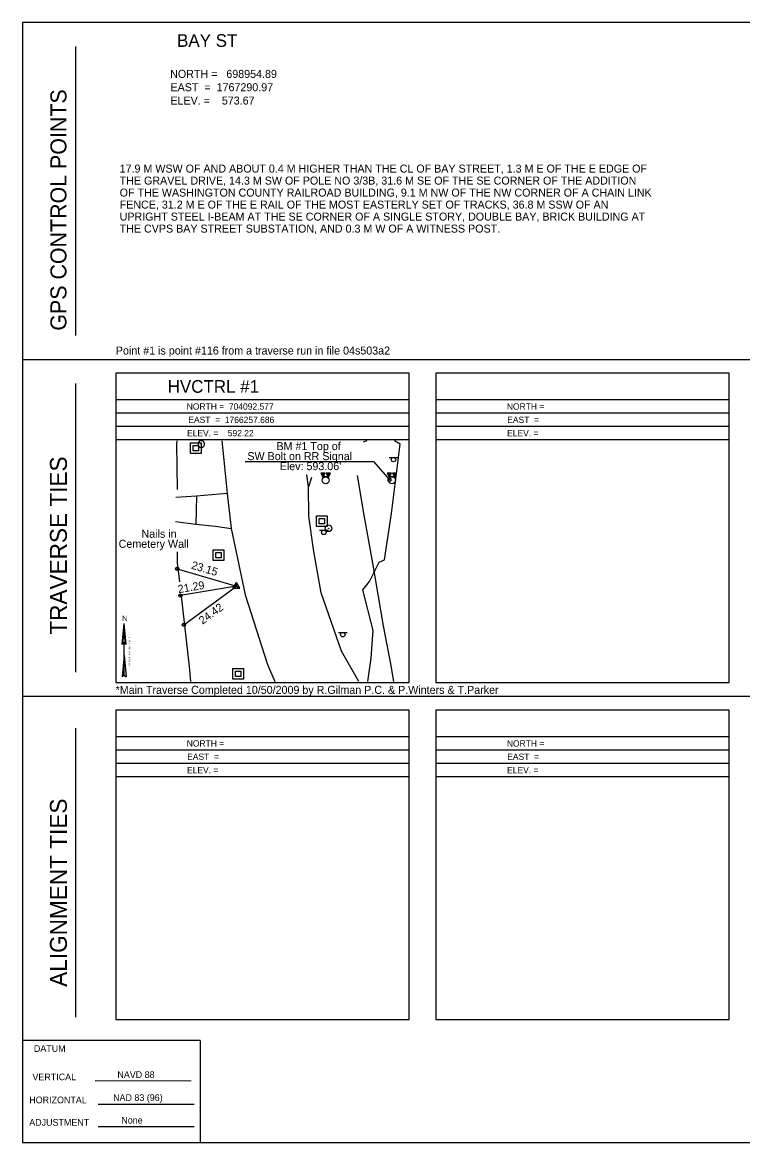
# Model space of a CAD drawing. Extents: x 1765437 to 1766077, y 703827 to 704247.
# Drawn here: x 1765437.5 to 1765707.5, y 703827.4 to 704247.4 of the extents above; entities that cross this region are included whole.
import ezdxf

# ---------------------------------------------------------------- set-up
doc = ezdxf.new("R2010")
doc.units = 0
for name, color, linetype in [('C_C', 7, 'Continuous'), ('CBP', 7, 'Continuous'), ('CPBM', 7, 'Continuous'), ('CPSM', 7, 'Continuous'), ('Default', 7, 'Continuous'), ('DS', 7, 'Continuous'), ('LW', 7, 'Continuous'), ('NBL1', 7, 'Continuous'), ('NBL2', 7, 'Continuous'), ('NNA_P', 7, 'Continuous'), ('PET', 7, 'Continuous'), ('RDG', 7, 'Continuous'), ('RDP', 7, 'Continuous'), ('RGP', 7, 'Continuous'), ('RRC', 7, 'Continuous'), ('SSGN', 7, 'Continuous'), ('TCSH', 7, 'Continuous')]:
    doc.layers.add(name, color=color, linetype=linetype)

msp = doc.modelspace()

# ---------------------------------------------------------------- linework, layer by layer
at = {"layer": 'C_C'}
for p, q in [((1765520.93, 704082.77), (1765569.04, 704082.77)), ((1765569.04, 704082.77), (1765575.07, 704075.83))]:
    msp.add_line(p, q, dxfattribs=at)
at = {"layer": 'CBP'}
for centre, radius in [((1765495.52, 704042.53), 0.625), ((1765495.52, 704042.53), 0.0833), ((1765496.71, 704032.44), 0.625), ((1765496.71, 704032.44), 0.0833), ((1765498.01, 704021.53), 0.625), ((1765498.01, 704021.53), 0.0833)]:
    msp.add_circle(centre, radius, dxfattribs=at)
at = {"layer": 'CPBM'}
for p, q in [((1765574.57, 704075.33), (1765574.57, 704076.33)), ((1765574.57, 704076.33), (1765575.57, 704076.33)), ((1765575.07, 704075.83), (1765575.07, 704075.83)), ((1765575.07, 704075.83), (1765575.07, 704075.83)), ((1765575.57, 704076.33), (1765575.57, 704075.33)), ((1765575.57, 704075.33), (1765574.57, 704075.33))]:
    msp.add_line(p, q, dxfattribs=at)
at = {"layer": 'CPSM'}
for p, q in [((1765516.47, 704035.22), (1765517.72, 704037.39)), ((1765516.47, 704035.22), (1765517.72, 704035.95)), ((1765516.47, 704035.22), (1765518.97, 704035.22)), ((1765518.97, 704035.22), (1765517.72, 704037.39)), ((1765517.72, 704035.95), (1765517.72, 704037.39)), ((1765517.72, 704035.95), (1765517.72, 704035.95)), ((1765517.72, 704035.95), (1765518.97, 704035.22))]:
    msp.add_line(p, q, dxfattribs=at)
at = {"layer": 'Default'}
for p, q in [((1765495.52, 704042.53), (1765517.72, 704035.95)), ((1765517.72, 704035.95), (1765496.71, 704032.44)), ((1765498.01, 704021.53), (1765517.72, 704035.95))]:
    msp.add_line(p, q, dxfattribs=at)
at = {"layer": 'DS'}
for p, q in [((1765500.51, 704089.75), (1765504.51, 704089.75)), ((1765500.51, 704085.75), (1765500.51, 704089.75)), ((1765501.51, 704086.75), (1765501.51, 704088.75)), ((1765501.51, 704088.75), (1765503.51, 704088.75)), ((1765503.51, 704088.75), (1765503.51, 704086.75)), ((1765504.51, 704089.75), (1765504.51, 704085.75)), ((1765504.51, 704085.75), (1765500.51, 704085.75)), ((1765503.51, 704086.75), (1765501.51, 704086.75)), ((1765502.51, 704087.75), (1765502.51, 704087.75)), ((1765502.51, 704087.75), (1765502.51, 704087.75)), ((1765547.67, 704062.35), (1765551.67, 704062.35)), ((1765547.67, 704058.35), (1765547.67, 704062.35)), ((1765548.67, 704059.35), (1765548.67, 704061.35)), ((1765548.67, 704061.35), (1765550.67, 704061.35)), ((1765550.67, 704059.35), (1765548.67, 704059.35)), ((1765549.67, 704060.35), (1765549.67, 704060.35)), ((1765549.67, 704060.35), (1765549.67, 704060.35)), ((1765550.67, 704061.35), (1765550.67, 704059.35)), ((1765551.67, 704062.35), (1765551.67, 704058.35)), ((1765551.67, 704058.35), (1765547.67, 704058.35)), ((1765508.97, 704049.66), (1765512.97, 704049.66)), ((1765508.97, 704045.66), (1765508.97, 704049.66)), ((1765509.97, 704046.66), (1765509.97, 704048.66)), ((1765509.97, 704048.66), (1765511.97, 704048.66)), ((1765511.97, 704046.66), (1765509.97, 704046.66)), ((1765510.98, 704047.67), (1765510.98, 704047.67)), ((1765510.98, 704047.67), (1765510.98, 704047.67)), ((1765511.97, 704048.66), (1765511.97, 704046.66)), ((1765512.97, 704049.66), (1765512.97, 704045.66)), ((1765512.97, 704045.66), (1765508.97, 704045.66)), ((1765516.4, 704005.15), (1765520.4, 704005.15)), ((1765516.4, 704001.15), (1765516.4, 704005.15)), ((1765517.4, 704002.15), (1765517.4, 704004.15)), ((1765517.4, 704004.15), (1765519.4, 704004.15)), ((1765519.4, 704004.15), (1765519.4, 704002.15)), ((1765520.4, 704005.15), (1765520.4, 704001.15)), ((1765520.4, 704001.15), (1765516.4, 704001.15)), ((1765519.4, 704002.15), (1765517.4, 704002.15)), ((1765518.4, 704003.15), (1765518.4, 704003.15)), ((1765518.4, 704003.15), (1765518.4, 704003.15))]:
    msp.add_line(p, q, dxfattribs=at)
at = {"layer": 'LW'}
for points in [[(1765495.34, 704090.48), (1765495.22, 704089.28), (1765495.48, 704072.19)], [(1765496.43, 704037.63), (1765495.6, 704044.8), (1765495.67, 704048.86)], [(1765500.62, 704000.23), (1765500.12, 704005.87), (1765497.06, 704032.21), (1765497.02, 704032.52)]]:
    msp.add_lwpolyline(points, dxfattribs=at)
at = {"layer": 'NBL1'}
msp.add_lwpolyline([(1765437.47, 703827.37), (1766077.47, 703827.37), (1766077.47, 704247.37), (1765437.47, 704247.37)], close=True, dxfattribs=at)
at = {"layer": 'NBL2'}
for p, q in [((1765457.47, 704130.04), (1765457.47, 704238.37)), ((1765437.47, 704121.04), (1766077.47, 704121.04)), ((1765457.47, 704003.7), (1765457.47, 704112.04)), ((1765582.47, 704105.87), (1765472.47, 704105.87)), ((1765702.47, 704105.87), (1765592.47, 704105.87)), ((1765582.47, 704100.87), (1765472.47, 704100.87)), ((1765702.47, 704100.87), (1765592.47, 704100.87)), ((1765582.47, 704095.87), (1765472.47, 704095.87)), ((1765702.47, 704095.87), (1765592.47, 704095.87)), ((1765582.47, 704090.87), (1765472.47, 704090.87)), ((1765702.47, 704090.87), (1765592.47, 704090.87)), ((1765437.47, 703994.7), (1766077.47, 703994.7)), ((1765457.47, 703874.37), (1765457.47, 703982.7)), ((1765582.47, 703979.54), (1765472.47, 703979.54)), ((1765702.47, 703979.54), (1765592.47, 703979.54)), ((1765582.47, 703974.54), (1765472.47, 703974.54)), ((1765702.47, 703974.54), (1765592.47, 703974.54)), ((1765582.47, 703969.54), (1765472.47, 703969.54)), ((1765702.47, 703969.54), (1765592.47, 703969.54)), ((1765582.47, 703964.54), (1765472.47, 703964.54)), ((1765702.47, 703964.54), (1765592.47, 703964.54)), ((1765504.13, 703865.62), (1765437.47, 703865.62)), ((1765504.13, 703865.62), (1765504.13, 703827.37)), ((1765504.13, 703865.62), (1765504.13, 703827.37)), ((1765464.71, 703850.6), (1765500.71, 703850.57)), ((1765465.82, 703841.83), (1765501.82, 703841.83)), ((1765465.82, 703833.39), (1765501.82, 703833.36))]:
    msp.add_line(p, q, dxfattribs=at)
for points in [[(1765472.47, 703999.87), (1765582.47, 703999.87), (1765582.47, 704115.87), (1765472.47, 704115.87)], [(1765592.47, 703999.87), (1765702.47, 703999.87), (1765702.47, 704115.87), (1765592.47, 704115.87)], [(1765472.47, 703873.54), (1765582.47, 703873.54), (1765582.47, 703989.54), (1765472.47, 703989.54)], [(1765592.47, 703873.54), (1765702.47, 703873.54), (1765702.47, 703989.54), (1765592.47, 703989.54)]]:
    msp.add_lwpolyline(points, close=True, dxfattribs=at)
at = {"layer": 'NNA_P'}
for p, q in [((1765474.92, 704014.17), (1765475.62, 704021.96)), ((1765475.62, 704002.59), (1765475.62, 704021.96)), ((1765476.31, 704014.17), (1765475.62, 704021.96)), ((1765474.92, 704014.17), (1765475.62, 704014.94)), ((1765476.31, 704014.17), (1765475.62, 704014.94)), ((1765475.62, 704010.11), (1765474.9, 704001.95)), ((1765475.62, 704010.11), (1765476.34, 704001.95)), ((1765475.62, 704002.59), (1765474.9, 704001.95)), ((1765475.62, 704002.59), (1765476.34, 704001.95))]:
    msp.add_line(p, q, dxfattribs=at)
at = {"layer": 'PET'}
for points in [[(1765512.23, 704090.48), (1765513.03, 704083.29), (1765514.25, 704070.75), (1765515.71, 704057.63), (1765520.98, 704032.77), (1765529.29, 704006.59), (1765532.11, 704000.23)], [(1765567, 704000.23), (1765568.17, 704009.02), (1765568.93, 704019.33), (1765565.04, 704034.6), (1765567.58, 704037.74), (1765571.24, 704044.99), (1765573.24, 704045.81), (1765575.83, 704063.3), (1765579.14, 704089.21), (1765576.93, 704090.48)], [(1765566.62, 704090.48), (1765565.24, 704089.99)], [(1765545.88, 704076.8), (1765544.71, 704073.22), (1765544.08, 704077.7)], [(1765563.59, 704000.23), (1765557.14, 704011.59), (1765549.5, 704033.49), (1765546.73, 704048.99), (1765544.83, 704062.24), (1765544.71, 704073.22)]]:
    msp.add_lwpolyline(points, dxfattribs=at)
at = {"layer": 'RDG'}
for points in [[(1765502.77, 704069.8), (1765494.94, 704069.3)], [(1765494.81, 704060.21), (1765502.43, 704059.19)]]:
    msp.add_lwpolyline(points, dxfattribs=at)
at = {"layer": 'RDP'}
msp.add_lwpolyline([(1765514.25, 704070.75), (1765502.77, 704069.8), (1765502.43, 704059.19), (1765509.81, 704058.46), (1765515.71, 704057.63)], dxfattribs=at)
at = {"layer": 'RGP'}
for p, q in [((1765504.99, 704090.48), (1765504.13, 704090.48)), ((1765504.56, 704089.3), (1765504.56, 704089.3)), ((1765552.25, 704057.69), (1765552.25, 704057.69))]:
    msp.add_line(p, q, dxfattribs=at)
for centre, radius in [((1765504.56, 704089.3), 0.0833), ((1765552.25, 704057.69), 1.25), ((1765552.25, 704057.69), 0.0833)]:
    msp.add_circle(centre, radius, dxfattribs=at)
msp.add_arc((1765504.56, 704089.3), 1.25, 110.1579, 69.8421, dxfattribs=at)
at = {"layer": 'RRC'}
msp.add_lwpolyline([(1765576.71, 704000.23), (1765575.57, 704006.88), (1765572.85, 704021.18), (1765568.79, 704044.56), (1765565.65, 704062.66), (1765563.08, 704077.44)], dxfattribs=at)
at = {"layer": 'SSGN'}
for p, q in [((1765574.93, 704084.29), (1765578.26, 704084.29)), ((1765576.57, 704083.46), (1765576.57, 704083.46)), ((1765548.83, 704056.97), (1765552.16, 704056.97)), ((1765550.47, 704056.14), (1765550.47, 704056.14)), ((1765555.94, 704018.65), (1765559.27, 704018.65)), ((1765557.58, 704017.82), (1765557.58, 704017.82))]:
    msp.add_line(p, q, dxfattribs=at)
for centre in [(1765576.57, 704083.46), (1765550.47, 704056.14), (1765557.58, 704017.82)]:
    msp.add_circle(centre, 0.833, dxfattribs=at)
at = {"layer": 'TCSH'}
for p, q in [((1765551, 704078.36), (1765549.33, 704078.36)), ((1765549.33, 704078.36), (1765550.1, 704077.03)), ((1765552.26, 704077.03), (1765550.1, 704077.03)), ((1765550.23, 704077.03), (1765551, 704078.36)), ((1765551.18, 704075.7), (1765551.18, 704075.7)), ((1765553.03, 704078.36), (1765551.37, 704078.36)), ((1765551.37, 704078.36), (1765552.14, 704077.03)), ((1765552.26, 704077.03), (1765553.03, 704078.36)), ((1765575.84, 704078.38), (1765574.17, 704078.38)), ((1765574.17, 704078.38), (1765574.94, 704077.05)), ((1765577.11, 704077.05), (1765574.94, 704077.05)), ((1765575.07, 704077.05), (1765575.84, 704078.38)), ((1765576.03, 704075.72), (1765576.03, 704075.72)), ((1765577.88, 704078.38), (1765576.21, 704078.38)), ((1765576.21, 704078.38), (1765576.98, 704077.05)), ((1765577.11, 704077.05), (1765577.88, 704078.38))]:
    msp.add_line(p, q, dxfattribs=at)
for points in [[(1765549.38, 704078.29), (1765550.95, 704078.29)], [(1765549.45, 704078.15), (1765550.88, 704078.15)], [(1765549.53, 704078.02), (1765550.8, 704078.02)], [(1765549.61, 704077.89), (1765550.72, 704077.89)], [(1765549.68, 704077.75), (1765550.65, 704077.75)], [(1765549.76, 704077.62), (1765550.57, 704077.62)], [(1765549.84, 704077.49), (1765550.49, 704077.49)], [(1765549.91, 704077.35), (1765550.41, 704077.35)], [(1765549.99, 704077.22), (1765550.34, 704077.22)], [(1765550.07, 704077.09), (1765550.26, 704077.09)], [(1765551.39, 704078.31), (1765553, 704078.31)], [(1765551.47, 704078.18), (1765552.93, 704078.18)], [(1765551.55, 704078.05), (1765552.85, 704078.05)], [(1765551.62, 704077.91), (1765552.77, 704077.91)], [(1765551.7, 704077.78), (1765552.7, 704077.78)], [(1765551.78, 704077.65), (1765552.62, 704077.65)], [(1765551.86, 704077.51), (1765552.54, 704077.51)], [(1765551.93, 704077.38), (1765552.47, 704077.38)], [(1765552.01, 704077.25), (1765552.39, 704077.25)], [(1765552.09, 704077.11), (1765552.31, 704077.11)], [(1765574.22, 704078.31), (1765575.8, 704078.31)], [(1765574.3, 704078.17), (1765575.72, 704078.17)], [(1765574.37, 704078.04), (1765575.64, 704078.04)], [(1765574.45, 704077.91), (1765575.57, 704077.91)], [(1765574.53, 704077.77), (1765575.49, 704077.77)], [(1765574.6, 704077.64), (1765575.41, 704077.64)], [(1765574.68, 704077.51), (1765575.34, 704077.51)], [(1765574.76, 704077.37), (1765575.26, 704077.37)], [(1765574.83, 704077.24), (1765575.18, 704077.24)], [(1765574.91, 704077.11), (1765575.1, 704077.11)], [(1765576.24, 704078.34), (1765577.85, 704078.34)], [(1765576.31, 704078.2), (1765577.77, 704078.2)], [(1765576.39, 704078.07), (1765577.69, 704078.07)], [(1765576.47, 704077.94), (1765577.62, 704077.94)], [(1765576.54, 704077.8), (1765577.54, 704077.8)], [(1765576.62, 704077.67), (1765577.46, 704077.67)], [(1765576.7, 704077.54), (1765577.39, 704077.54)], [(1765576.78, 704077.4), (1765577.31, 704077.4)], [(1765576.85, 704077.27), (1765577.23, 704077.27)], [(1765576.93, 704077.14), (1765577.16, 704077.14)]]:
    msp.add_lwpolyline(points, dxfattribs=at)
for centre in [(1765551.18, 704075.7), (1765576.03, 704075.72)]:
    msp.add_circle(centre, 1.33, dxfattribs=at)

# ---------------------------------------------------------------- texts
at = {"layer": 'C_C'}
for s, p in [('BM #1 Top of', (1765532.72, 704087.01)), ('SW Bolt on RR Signal', (1765521.81, 704083.25)), ("Elev: 593.06'", (1765533.93, 704079.5)), ('Nails in', (1765482.11, 704054.14)), ('Cemetery Wall', (1765473.54, 704050.38))]:
    msp.add_text(s, height=3, dxfattribs=at).set_placement(p)
at = {"layer": 'Default'}
for s, p in [('17.9 M WSW OF AND ABOUT 0.4 M HIGHER THAN THE CL OF BAY STREET, 1.3 M E OF THE E EDGE OF ', (1765473.92, 704191.06)), ('THE GRAVEL DRIVE, 14.3 M SW OF POLE NO 3/3B, 31.6 M SE OF THE SE CORNER OF THE ADDITION ', (1765473.92, 704186.56)), ('OF THE WASHINGTON COUNTY RAILROAD BUILDING, 9.1 M NW OF THE NW CORNER OF A CHAIN LINK ', (1765473.92, 704182.06)), ('FENCE, 31.2 M E OF THE E RAIL OF THE MOST EASTERLY SET OF TRACKS, 36.8 M SSW OF AN ', (1765473.92, 704177.56)), ('UPRIGHT STEEL I-BEAM AT THE SE CORNER OF A SINGLE STORY, DOUBLE BAY, BRICK BUILDING AT ', (1765473.92, 704173.06)), ('THE CVPS BAY STREET SUBSTATION, AND 0.3 M W OF A WITNESS POST.', (1765473.92, 704168.56)), ('Point #1 is point #116 from a traverse run in file 04s503a2', (1765472.5, 704122.84)), ('*Main Traverse Completed 10/50/2009 by R.Gilman P.C. & P.Winters & T.Parker', (1765472.41, 703995.62))]:
    msp.add_text(s, height=3, dxfattribs=at).set_placement(p)
for s, rotation, p in [('23.15', 343.4693, (1765500.54, 704042.61)), ('21.29', 9.4682, (1765496, 704033.36)), ('24.42', 36.1927, (1765504.99, 704021.5))]:
    msp.add_text(s, height=3, rotation=rotation, dxfattribs=at).set_placement(p)
at = {"layer": 'NBL2'}
for s, height, p in [('       BAY ST      ', 4.75, (1765483.11, 704238.2)), ('NORTH =   698954.89 ', 3, (1765492.85, 704226.57)), ('EAST  =  1767290.97 ', 3, (1765492.99, 704221.57)), ('ELEV. =    573.67   ', 3, (1765492.95, 704216.57)), ('     HVCTRL #1     ', 4.75, (1765483.11, 704108.5)), ('NORTH =  704092.577 ', 2.375, (1765499.08, 704102.18)), ('NORTH =             ', 2.375, (1765619.08, 704102.18)), ('EAST  =  1766257.686', 2.375, (1765499.67, 704097.18)), ('EAST  =             ', 2.375, (1765619.23, 704097.18)), ('ELEV. =    592.22   ', 2.375, (1765499.19, 704092.18)), ('ELEV. =             ', 2.375, (1765619.19, 704092.18)), ('NORTH =             ', 2.375, (1765499.08, 703975.85)), ('NORTH =             ', 2.375, (1765619.08, 703975.85)), ('EAST  =             ', 2.375, (1765499.23, 703970.85)), ('EAST  =             ', 2.375, (1765619.23, 703970.85)), ('ELEV. =             ', 2.375, (1765499.19, 703965.85)), ('ELEV. =             ', 2.375, (1765619.19, 703965.85)), ('DATUM', 2.5, (1765441.78, 703861.39)), ('  NAVD 88 ', 2.5, (1765471.23, 703851.61)), ('HORIZONTAL', 2.5, (1765440.04, 703842.12)), ('NAD 83 (96)', 2.5, (1765471.47, 703843)), ('ADJUSTMENT', 2.5, (1765440.04, 703833.69)), ('   None   ', 2.5, (1765471.77, 703834.51))]:
    msp.add_text(s, height=height, dxfattribs=at).set_placement(p)
for s, height, rotation, p in [('GPS CONTROL POINTS', 6, 90, (1765453.97, 704131.79)), ('TRAVERSE TIES', 6.3332, 90, (1765454.13, 704017.81)), ('ALIGNMENT TIES', 6.3332, 90, (1765454.13, 703885.78)), ('VERTICAL', 2.5, 0.1439, (1765441.24, 703850.72))]:
    msp.add_text(s, height=height, rotation=rotation, dxfattribs=at).set_placement(p)
at = {"layer": 'NNA_P'}
msp.add_text('N', height=1.97, dxfattribs=at).set_placement((1765474.86, 704022.98))
msp.add_text('VT STATE PLANE GRID', height=0.7, rotation=90.0204, dxfattribs=at).set_placement((1765477.97, 704006.15))

doc.saveas('drawing.dxf')
